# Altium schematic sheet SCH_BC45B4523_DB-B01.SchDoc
size A4
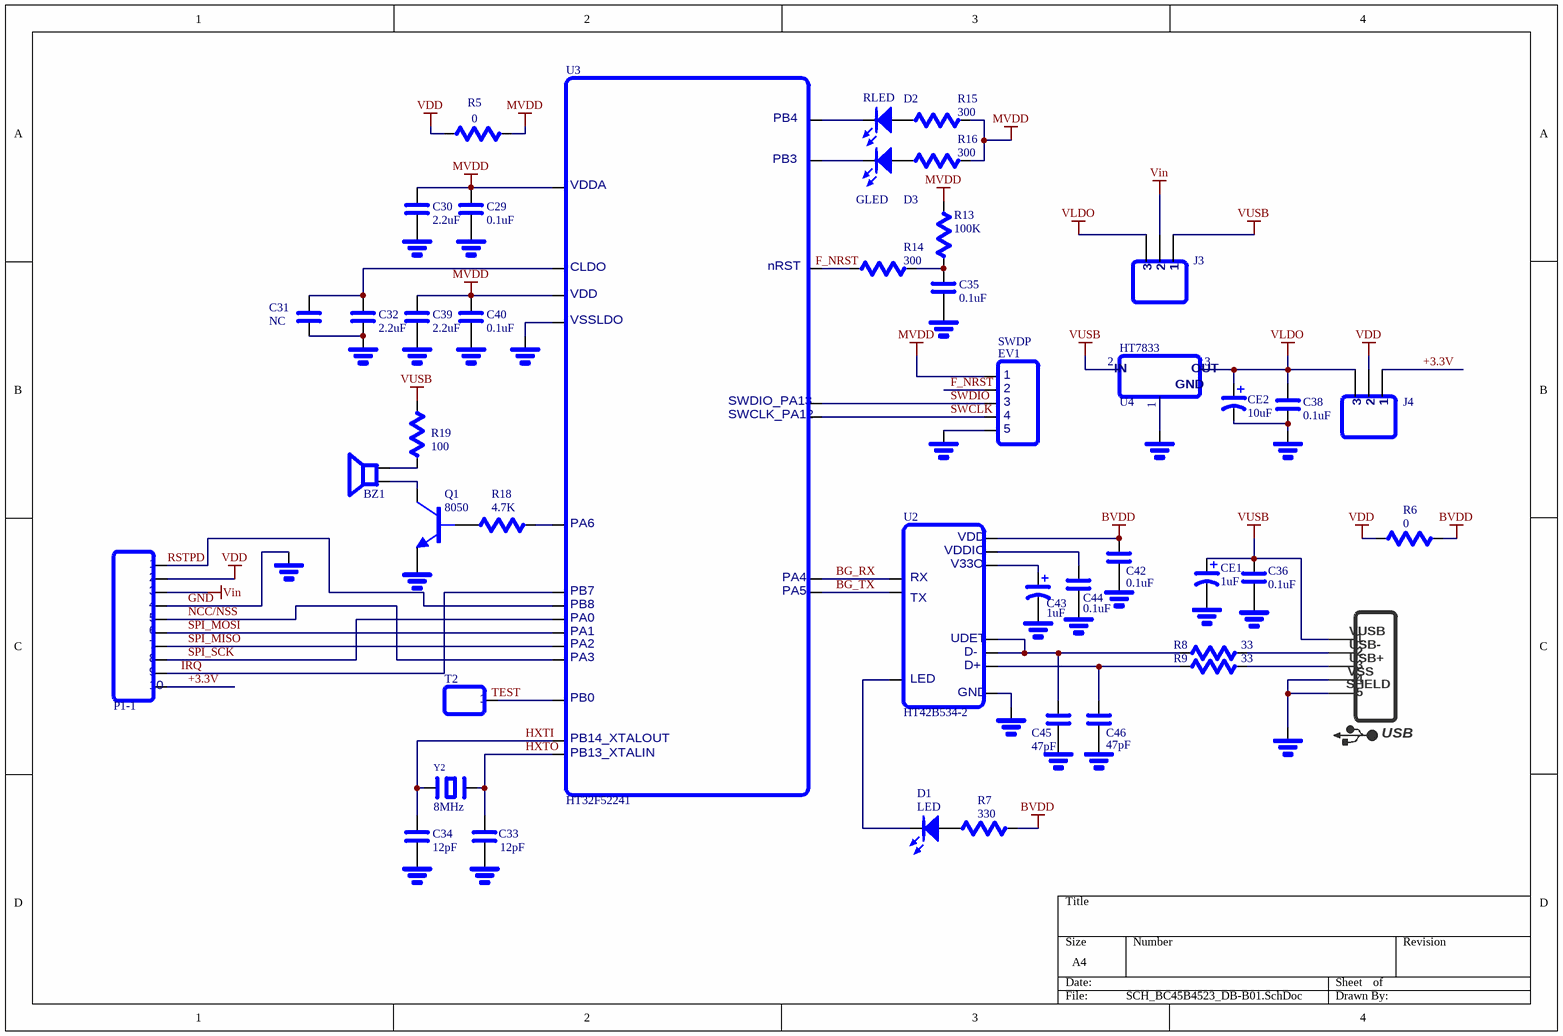
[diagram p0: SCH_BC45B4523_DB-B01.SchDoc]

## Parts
(Parts that share a designator on the sheet are numbered #1, #2 ... from top to bottom, then left to right.)
*#1  GND(1)  (value not drawn)
*#2  GND(1)  (value not drawn)
*#3  GND(1)  (value not drawn)
*#4  GND(1)  (value not drawn)
*#5  GND(1)  (value not drawn)
*#6  GND(1)  (value not drawn)
*#7  GND(1)  (value not drawn)
*#8  GND(1)  (value not drawn)
*#9  GND(1)  (value not drawn)
*#10  GND(1)  (value not drawn)
*#11  GND(1)  (value not drawn)
*#12  GND(1)  (value not drawn)
*#13  GND(1)  (value not drawn)
*#14  GND(1)  (value not drawn)
*#15  GND(1)  (value not drawn)
*#16  GND(1)  (value not drawn)
*#17  GND(1)  (value not drawn)
*#18  T2
*#19  GND(1)  (value not drawn)
*#20  GND(1)  (value not drawn)
*#21  GND(1)  (value not drawn)
*#22  GND(1)  (value not drawn)
*#23  GND(1)  (value not drawn)
*#24  GND(1)  (value not drawn)
BZ1  Speaker(1)  [PIN2]  (value not drawn)
C29  0.1uF
C30  2.2uF
C31  NC
C32  2.2uF
C33  12pF
C34  12pF
C35  0.1uF
C36  0.1uF
C38  0.1uF
C39  2.2uF
C40  0.1uF
C42  0.1uF
C43  1uF
C44  0.1uF
C45  47pF
C46  47pF
CE1  1uF
CE2  10uF
EV1  SWDP
GLED  D3  [LED3M]
HT7833  U4  [SOT23-5]
J3  CON3  (value not drawn)
J4  CON3  (value not drawn)
LED  D1  [LED3M]
P1-1  CON*10  (value not drawn)
Q1  8050  [TO-226-AA]
R5  0
R6  0
R7  330
R8  33
R9  33
R13  100K
R14  300
R15  300
R16  300
R18  4.7K
R19  100
RLED  D2  [LED3M]
U2  HT42B534-2
U3  HT32F52241
U???  MIcro USB  (value not drawn)
Y2  8MHz  [XTAL-49US]

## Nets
BVDD: C42.2 R6.1 R7.1 U2.10
MVDD: C29.1 C30.1 C39.1 C40.1 EV1.15 R5.1 R13.1 R15.1 R16.1 U3.4(MOSI) U3.6(PDN)
VDD: J4.3(VSS) P1-1.16 R5.2 R6.2
Vin: J3.3(VSS) P1-1.17
VLDO: C38.1 CE2.1 HT7833.3(Vout) J3.3(VSS) J4.3(VSS)
VUSB: C36.2 CE1.1 HT7833.2(Vin) J3.2(VSS) R19.2 U???.1(VDD)
+3.3V: J4.2(VSS) P1-1.18
BG_RX: U2.2 U3.1(VDD)
BG_TX: U2.3 U3.4(MOSI)
F_NRST: EV1.16
GND: *#11.?1 P1-1.16
HXTI: C34.1 U3.10(EXINT) Y2.1(OSC1)
HXTO: C33.1 U3.1(VDD) Y2.2(OSC2)
IRQ: P1-1.17 U3.2(SPICSN)
NCC/NSS: P1-1.17 U3.2(SPICSN)
RSTPD: P1-1.15 U3.2(SPICSN)
SPI_MISO: P1-1.16 U3.2(SPICSN)
SPI_MOSI: P1-1.17 U3.4(MOSI)
SPI_SCK: P1-1.17 U3.4(MOSI)
SWCLK: EV1.16 U3.4(MOSI)
SWDIO: EV1.17 U3.1(VDD)
Net*#1_?1: *#1.?1 C30.2
Net*#2_?1: *#2.?1 C29.2
Net*#3_?1: *#3.?1 C35.1
Net*#4_?1: *#4.?1 C31.2 C32.2
Net*#5_?1: *#5.?1 C39.2
Net*#6_?1: *#6.?1 C40.2
Net*#7_?1: *#7.?1 U3.2(SPICSN)
Net*#8_?1: *#8.?1 EV1.17
Net*#9_?1: *#9.?1 HT7833.1(GND)
Net*#10_?1: *#10.?1 C38.2 CE2.2
Net*#12_?1: *#12.?1 Q1.3(E)
Net*#13_?1: *#13.?1 C42.1
Net*#14_?1: *#14.?1 CE1.2
Net*#15_?1: *#15.?1 C36.1
Net*#16_?1: *#16.?1 C44.1
Net*#17_?1: *#17.?1 C43.2
Net*#18_15: *#18.15 U3.2(SPICSN)
Net*#19_?1: *#19.?1 U2.4(MOSI)
Net*#20_?1: *#20.?1 U???.4(GND) U???.5(GND)
Net*#21_?1: *#21.?1 C45.1
Net*#22_?1: *#22.?1 C46.1
Net*#23_?1: *#23.?1 C34.2
Net*#24_?1: *#24.?1 C33.2
NetBZ1_1: BZ1.1 Q1.1(C)
NetBZ1_2: BZ1.2 R19.1
NetC31_1: C31.1 C32.1 U3.2(SPICSN)
NetC35_2: C35.2 R13.2 R14.1
NetC43_1: C43.1 U2.9(STATE)
NetC44_2: C44.2 U2.8(WAKEUP)
NetC45_2: C45.2 R8.2 U2.1 U2.11
NetC46_2: C46.2 R9.2 U2.11
NetGLED_1: GLED.1(A) R16.2
NetGLED_2: GLED.2(K) U3.8(WAKEUP)
NetLED_1: LED.1(A) R7.2
NetLED_2: LED.2(K) U2.10
NetQ1_2: Q1.2(B) R18.2
NetR8_1: R8.1 U???.2(D+)
NetR9_1: R9.1 U???.3(D-)
NetR14_2: R14.2 U3.9(STATE)
NetR15_2: R15.2 RLED.1(A)
NetR18_1: R18.1 U3.8(WAKEUP)
NetRLED_2: RLED.2(K) U3.10(EXINT)

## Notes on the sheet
- Labels drawn without touching a wire or pin: F_NRST, TEST

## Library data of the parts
*#1-*#17 *#19-*#24 = GND(1): GND
*#18 = CON*1
BZ1 = Speaker(1): Loudspeaker
C29-C36 C38-C40 C42 C44-C46 = Cap(1): Capacitor
C43 CE1 CE2 = Cap(3)
EV1 = CON*5
GLED LED RLED = LED(1): Typical INFRARED GaAs LED
HT7833 = LDO
Q1 = NPN(1): NPN Bipolar Transistor
R5-R9 R13-R16 R18 R19 = Resistor(1): Resisitor
U2 = HT42B5x4: IC
U3 = HT32F52241: IC
U??? = USB_2
Y2 = Xtal(1)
